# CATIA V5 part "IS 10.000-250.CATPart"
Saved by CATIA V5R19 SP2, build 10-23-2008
Part number: IS 10.000-250
Bounding box of the stored display mesh (mm): x -97.324 to 97.324, y -97.5 to 97.5, z 0 to 660
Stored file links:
  C:\Users\Bora\Desktop\3D Katı model\IS serisi\IS 10.000\IS 10.000-250.CATPart
  C:\Program Files\Dassault Systemes\B19\intel_a\reffiles\standard\MetricThickPitch.txt
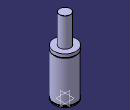
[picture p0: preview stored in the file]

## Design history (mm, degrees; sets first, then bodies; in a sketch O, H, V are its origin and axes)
Body1 (main body)
  Sketch1 on yz-plane, origin (0, 0, 0), H (0, 1, 0), V (0, 0, 1)
    point P1 (97.5, 379)
    point P2 (97.5, 374)
    point P5 (47.5, 659)
    point P7 (47.5, 659)
    point P12 (97.5, 374)
    point P13 (97.5, 379)
    arc A1 centre (97.5, 376.5) radius 2.5 from (97.5, 379) to (97.5, 374) ccw
    line L1 (97.5, 0) -> (97.5, 8)
    line L2 (47.5, 659) -> (47.5, 407)
    arc A2 centre (46.5, 659) radius 1 from (47.5, 659) to (46.5, 660) ccw
    line L3 (93.5, 16) -> (93.5, 8)
    line L4 (97.5, 16) -> (97.5, 374)
    line L5 (97.5, 379) -> (97.5, 407)
    line L6 (46.5, 660) -> (0, 660)
    line L7 (47.5, 407) -> (97.5, 407)
    line L8 (97.5, 16) -> (93.5, 16)
    line L9 (93.5, 8) -> (97.5, 8)
    line L10 (97.5, 0) -> (0, 0)
    tangency: L6 A2
    horizontal: L7 H, L8 H, L9 H, L10 H
    coincidence: P1 P13, P2 P12, P5 P7
  Shaft1: profile Sketch1, axis Sketch1.V, angle 360
  Sketch2 on face of Shaft1 from Sketch1.L10, origin (0, 0, 0), H (1, 0, 0), V (0, -1, 0)
    point P1 (60, 0)
    distance P1 V = 60
  Hole1: placed by Sketch2, at (60, 0, 0) direction (0, 0, 1), diameter 10.106, depth 16, threaded "M12", thread diameter 12, thread depth 16, pitch 1.75
  CircPattern1: of Hole1, instances 4, angular step 90, axis from xy-plane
